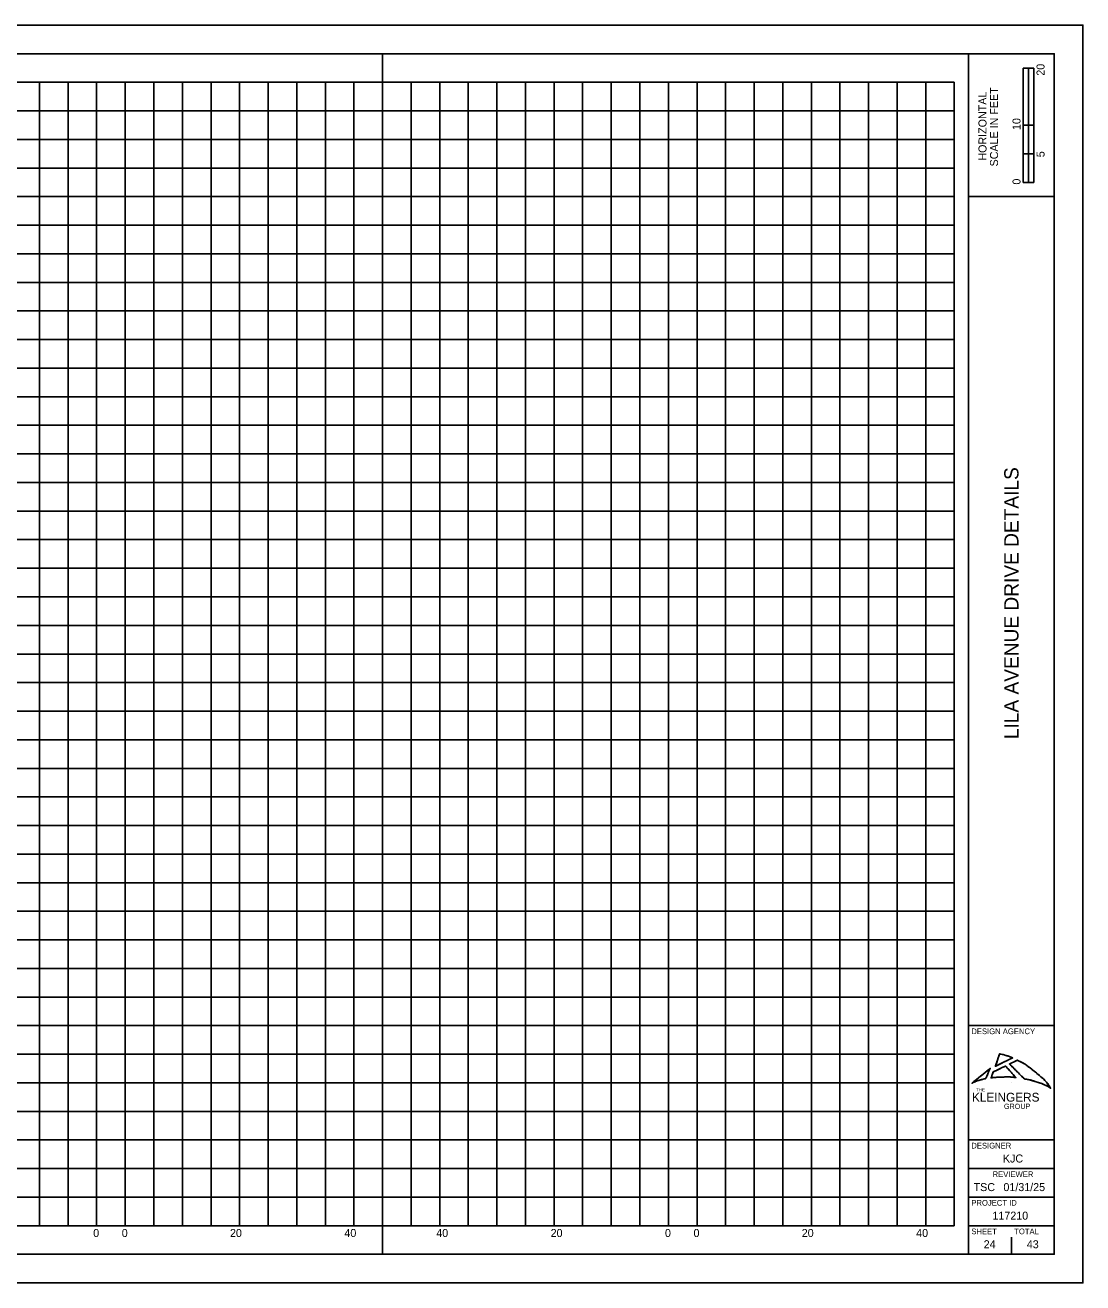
# Model space of a CAD drawing. Extents: x -2.9 to 34, y 0 to 23.9.
# Drawn here: x 15.5 to 34, y 0 to 22 of the extents above; entities that cross this region are included whole.
import ezdxf

# ---------------------------------------------------------------- set-up
doc = ezdxf.new("R2010")
doc.units = 0
for name, color, linetype in [('Default', 7, 'Continuous'), ('SH_Border', 7, 'Continuous'), ('SH_Cut_Line', 7, 'Continuous'), ('SH_Data', 7, 'Continuous'), ('SH_Major_Grid_Line', 7, 'Continuous')]:
    doc.layers.add(name, color=color, linetype=linetype)

msp = doc.modelspace()

# ---------------------------------------------------------------- linework, layer by layer
at = {"layer": 'Default'}
for points, degree in [([(32.542, 4.004), (32.542, 4.004), (32.47, 3.788), (32.47, 3.788)], 2), ([(32.772, 3.935), (32.772, 3.935), (32.722, 3.958), (32.655, 3.979), (32.588, 3.999), (32.542, 4.004), (32.542, 4.004), (32.542, 4.004), (32.47, 3.788), (32.47, 3.788), (32.47, 3.788), (32.772, 3.935), (32.772, 3.935)], 3), ([(32.772, 3.935), (32.772, 3.935), (32.722, 3.958), (32.655, 3.979)], 2), ([(32.379, 3.752), (32.379, 3.752), (32.061, 3.492), (32.061, 3.492)], 2), ([(32.379, 3.752), (32.379, 3.752), (32.061, 3.492), (32.061, 3.492), (32.061, 3.492), (32.133, 3.529), (32.21, 3.55), (32.28, 3.569), (32.303, 3.572), (32.303, 3.572), (32.303, 3.572), (32.379, 3.752), (32.379, 3.752)], 3), ([(32.303, 3.572), (32.303, 3.572), (32.379, 3.752), (32.379, 3.752)], 2), ([(32.648, 3.793), (32.648, 3.793), (32.83, 3.589), (32.83, 3.589), (32.83, 3.589), (32.734, 3.604), (32.602, 3.6), (32.455, 3.595), (32.396, 3.584), (32.396, 3.584), (32.396, 3.584), (32.434, 3.691), (32.434, 3.691), (32.434, 3.691), (32.648, 3.793), (32.648, 3.793)], 3), ([(32.434, 3.691), (32.434, 3.691), (32.648, 3.793), (32.648, 3.793)], 2), ([(32.47, 3.788), (32.47, 3.788), (32.772, 3.935), (32.772, 3.935)], 2), ([(32.648, 3.793), (32.648, 3.793), (32.83, 3.589), (32.83, 3.589)], 2), ([(33.2, 3.512), (33.079, 3.551), (32.978, 3.567), (32.978, 3.567), (32.978, 3.567), (32.717, 3.827), (32.717, 3.827), (32.717, 3.827), (32.855, 3.894), (32.855, 3.894), (32.855, 3.894), (32.985, 3.834), (33.142, 3.708), (33.348, 3.542), (33.438, 3.405), (33.438, 3.405), (33.438, 3.405), (33.351, 3.463), (33.2, 3.512)], 3), ([(32.717, 3.827), (32.717, 3.827), (32.855, 3.894), (32.855, 3.894)], 2), ([(32.978, 3.567), (32.978, 3.567), (32.717, 3.827), (32.717, 3.827)], 2), ([(32.855, 3.894), (32.855, 3.894), (32.985, 3.834), (33.142, 3.708)], 2), ([(32.061, 3.492), (32.061, 3.492), (32.133, 3.529), (32.21, 3.55)], 2), ([(32.21, 3.55), (32.28, 3.569), (32.303, 3.572), (32.303, 3.572)], 2), ([(32.396, 3.584), (32.396, 3.584), (32.434, 3.691), (32.434, 3.691)], 2), ([(32.602, 3.6), (32.455, 3.595), (32.396, 3.584), (32.396, 3.584)], 2), ([(32.83, 3.589), (32.83, 3.589), (32.734, 3.604), (32.602, 3.6)], 2), ([(33.2, 3.512), (33.079, 3.551), (32.978, 3.567), (32.978, 3.567)], 2), ([(33.142, 3.708), (33.348, 3.542), (33.438, 3.405), (33.438, 3.405)], 2), ([(33.438, 3.405), (33.438, 3.405), (33.351, 3.463), (33.2, 3.512)], 2)]:
    msp.add_open_spline(points, degree=degree, dxfattribs=at)
at = {"layer": 'SH_Border'}
for p, q in [((21.752, 0.5), (21.752, 21.5)), ((32, 0.5), (32, 21.5)), ((32, 19), (33.5, 19)), ((32, 4.5), (33.5, 4.5)), ((32, 2.5), (33.5, 2.5)), ((32, 2), (33.5, 2)), ((32, 1.5), (33.5, 1.5)), ((32, 1), (33.5, 1))]:
    msp.add_line(p, q, dxfattribs=at)
msp.add_lwpolyline([(1.5, 21.5), (33.5, 21.5), (33.5, 0.5), (1.5, 0.5)], close=True, dxfattribs=at)
at = {"layer": 'SH_Cut_Line'}
msp.add_lwpolyline([(0, 0), (34, 0), (34, 22), (0, 22)], close=True, dxfattribs=at)
at = {"layer": 'SH_Data'}
for p, q in [((32.957, 19.25), (32.957, 21.25)), ((33.144, 21.25), (32.957, 21.25)), ((32.957, 20.25), (32.957, 21.25)), ((32.957, 21.25), (33.05, 21.25)), ((33.05, 21.25), (33.051, 21.25)), ((33.051, 21.25), (33.051, 20.25)), ((33.144, 21.25), (33.144, 19.25)), ((33.051, 20.25), (32.957, 20.25)), ((33.143, 20.25), (33.05, 20.25)), ((33.05, 20.25), (33.05, 19.75)), ((33.143, 19.75), (33.143, 20.25)), ((33.05, 19.75), (32.957, 19.75)), ((32.957, 19.75), (32.957, 19.25)), ((33.05, 19.75), (33.143, 19.75)), ((33.05, 19.25), (33.05, 19.75)), ((33.144, 19.25), (32.957, 19.25)), ((32.957, 19.25), (33.05, 19.25)), ((32.75, 3.5), (32.75, 3.5)), ((32.375, 0.675), (32.375, 0.675)), ((32.75, 0.5), (32.75, 0.8))]:
    msp.add_line(p, q, dxfattribs=at)
at = {"layer": 'SH_Major_Grid_Line'}
for p, q in [((1.752, 21), (16.752, 21)), ((15.752, 11), (15.752, 21)), ((16.252, 11), (16.252, 21)), ((16.752, 11), (16.752, 21)), ((16.752, 11), (16.752, 21)), ((16.752, 21), (31.752, 21)), ((17.252, 11), (17.252, 21)), ((17.752, 11), (17.752, 21)), ((18.252, 11), (18.252, 21)), ((18.752, 11), (18.752, 21)), ((19.252, 11), (19.252, 21)), ((19.752, 11), (19.752, 21)), ((20.252, 11), (20.252, 21)), ((20.752, 11), (20.752, 21)), ((21.252, 11), (21.252, 21)), ((21.752, 11), (21.752, 21)), ((22.252, 11), (22.252, 21)), ((22.752, 11), (22.752, 21)), ((23.252, 11), (23.252, 21)), ((23.752, 11), (23.752, 21)), ((24.252, 11), (24.252, 21)), ((24.752, 11), (24.752, 21)), ((25.252, 11), (25.252, 21)), ((25.752, 11), (25.752, 21)), ((26.252, 11), (26.252, 21)), ((26.752, 11), (26.752, 21)), ((27.252, 11), (27.252, 21)), ((27.752, 11), (27.752, 21)), ((28.252, 11), (28.252, 21)), ((28.752, 11), (28.752, 21)), ((29.252, 11), (29.252, 21)), ((29.752, 11), (29.752, 21)), ((30.252, 11), (30.252, 21)), ((30.752, 11), (30.752, 21)), ((31.252, 11), (31.252, 21)), ((31.752, 11), (31.752, 21)), ((1.752, 20.5), (16.752, 20.5)), ((16.752, 20.5), (31.752, 20.5)), ((1.752, 20), (16.752, 20)), ((16.752, 20), (31.752, 20)), ((1.752, 19.5), (16.752, 19.5)), ((16.752, 19.5), (31.752, 19.5)), ((1.752, 19), (16.752, 19)), ((16.752, 19), (31.752, 19)), ((1.752, 18.5), (16.752, 18.5)), ((16.752, 18.5), (31.752, 18.5)), ((1.752, 18), (16.752, 18)), ((16.752, 18), (31.752, 18)), ((1.752, 17.5), (16.752, 17.5)), ((16.752, 17.5), (31.752, 17.5)), ((1.752, 17), (16.752, 17)), ((16.752, 17), (31.752, 17)), ((1.752, 16.5), (16.752, 16.5)), ((16.752, 16.5), (31.752, 16.5)), ((1.752, 16), (16.752, 16)), ((16.752, 16), (31.752, 16)), ((1.752, 15.5), (16.752, 15.5)), ((16.752, 15.5), (31.752, 15.5)), ((1.752, 15), (16.752, 15)), ((16.752, 15), (31.752, 15)), ((1.752, 14.5), (16.752, 14.5)), ((16.752, 14.5), (31.752, 14.5)), ((1.752, 14), (16.752, 14)), ((16.752, 14), (31.752, 14)), ((1.752, 13.5), (16.752, 13.5)), ((16.752, 13.5), (31.752, 13.5)), ((1.752, 13), (16.752, 13)), ((16.752, 13), (31.752, 13)), ((1.752, 12.5), (16.752, 12.5)), ((16.752, 12.5), (31.752, 12.5)), ((1.752, 12), (16.752, 12)), ((16.752, 12), (31.752, 12)), ((1.752, 11.5), (16.752, 11.5)), ((16.752, 11.5), (31.752, 11.5)), ((1.752, 11), (16.752, 11)), ((16.752, 11), (31.752, 11)), ((1.752, 11), (16.752, 11)), ((15.752, 1), (15.752, 11)), ((16.252, 1), (16.252, 11)), ((16.752, 11), (31.752, 11)), ((16.752, 1), (16.752, 11)), ((16.752, 1), (16.752, 11)), ((17.252, 1), (17.252, 11)), ((17.752, 1), (17.752, 11)), ((18.252, 1), (18.252, 11)), ((18.752, 1), (18.752, 11)), ((19.252, 1), (19.252, 11)), ((19.752, 1), (19.752, 11)), ((20.252, 1), (20.252, 11)), ((20.752, 1), (20.752, 11)), ((21.252, 1), (21.252, 11)), ((21.752, 1), (21.752, 11)), ((22.252, 1), (22.252, 11)), ((22.752, 1), (22.752, 11)), ((23.252, 1), (23.252, 11)), ((23.752, 1), (23.752, 11)), ((24.252, 1), (24.252, 11)), ((24.752, 1), (24.752, 11)), ((25.252, 1), (25.252, 11)), ((25.752, 1), (25.752, 11)), ((26.252, 1), (26.252, 11)), ((26.752, 1), (26.752, 11)), ((27.252, 1), (27.252, 11)), ((27.752, 1), (27.752, 11)), ((28.252, 1), (28.252, 11)), ((28.752, 1), (28.752, 11)), ((29.252, 1), (29.252, 11)), ((29.752, 1), (29.752, 11)), ((30.252, 1), (30.252, 11)), ((30.752, 1), (30.752, 11)), ((31.252, 1), (31.252, 11)), ((31.752, 1), (31.752, 11)), ((1.752, 10.5), (16.752, 10.5)), ((16.752, 10.5), (31.752, 10.5)), ((1.752, 10), (16.752, 10)), ((16.752, 10), (31.752, 10)), ((1.752, 9.5), (16.752, 9.5)), ((16.752, 9.5), (31.752, 9.5)), ((1.752, 9), (16.752, 9)), ((16.752, 9), (31.752, 9)), ((1.752, 8.5), (16.752, 8.5)), ((16.752, 8.5), (31.752, 8.5)), ((1.752, 8), (16.752, 8)), ((16.752, 8), (31.752, 8)), ((1.752, 7.5), (16.752, 7.5)), ((16.752, 7.5), (31.752, 7.5)), ((1.752, 7), (16.752, 7)), ((16.752, 7), (31.752, 7)), ((1.752, 6.5), (16.752, 6.5)), ((16.752, 6.5), (31.752, 6.5)), ((1.752, 6), (16.752, 6)), ((16.752, 6), (31.752, 6)), ((1.752, 5.5), (16.752, 5.5)), ((16.752, 5.5), (31.752, 5.5)), ((1.752, 5), (16.752, 5)), ((16.752, 5), (31.752, 5)), ((1.752, 4.5), (16.752, 4.5)), ((16.752, 4.5), (31.752, 4.5)), ((1.752, 4), (16.752, 4)), ((16.752, 4), (31.752, 4)), ((1.752, 3.5), (16.752, 3.5)), ((16.752, 3.5), (31.752, 3.5)), ((1.752, 3), (16.752, 3)), ((16.752, 3), (31.752, 3)), ((1.752, 2.5), (16.752, 2.5)), ((16.752, 2.5), (31.752, 2.5)), ((1.752, 2), (16.752, 2)), ((16.752, 2), (31.752, 2)), ((1.752, 1.5), (16.752, 1.5)), ((16.752, 1.5), (31.752, 1.5)), ((1.752, 1), (16.752, 1)), ((16.752, 1), (31.752, 1))]:
    msp.add_line(p, q, dxfattribs=at)

# ---------------------------------------------------------------- texts
at = {"layer": 'Default'}
for s, height, p in [('KLEINGERS', 0.1542, (32.061, 3.17)), ('THE', 0.0561, (32.135, 3.349)), ('GROUP', 0.0911, (32.62, 3.042))]:
    msp.add_text(s, height=height, dxfattribs=at).set_placement(p)
at = {"layer": 'SH_Border'}
for s, p in [('0', (16.692, 0.802)), ('0', (17.191, 0.802)), ('20', (19.084, 0.802)), ('40', (21.085, 0.802)), ('40', (22.692, 0.802)), ('20', (24.692, 0.802)), ('0', (26.692, 0.802)), ('0', (27.191, 0.802)), ('20', (29.084, 0.802)), ('40', (31.085, 0.802))]:
    msp.add_text(s, height=0.14, dxfattribs=at).set_placement(p)
at = {"layer": 'SH_Data'}
for s, height, p in [('20', 0.14, (33.33, 21.116)), ('SCALE IN FEET', 0.14, (32.517, 19.529)), ('HORIZONTAL', 0.14, (32.315, 19.63)), ('10', 0.14, (32.91, 20.166)), ('5', 0.14, (33.33, 19.69)), ('0', 0.14, (32.91, 19.211)), ('LILA AVENUE DRIVE DETAILS', 0.25, (32.875, 9.511))]:
    msp.add_text(s, height=height, rotation=90, dxfattribs=at).set_placement(p)
for s, height, p in [('DESIGN AGENCY', 0.1, (32.05, 4.35)), ('DESIGNER', 0.1, (32.05, 2.35)), ('KJC', 0.14, (32.602, 2.105)), ('REVIEWER', 0.1, (32.422, 1.85)), ('TSC', 0.14, (32.09, 1.605)), ('01/31/25', 0.14, (32.611, 1.605)), ('PROJECT ID', 0.1, (32.05, 1.35)), ('117210', 0.14, (32.419, 1.105)), ('SHEET', 0.1, (32.05, 0.85)), ('TOTAL', 0.1, (32.8, 0.85)), ('24', 0.14, (32.266, 0.605)), ('43', 0.14, (33.02, 0.605))]:
    msp.add_text(s, height=height, dxfattribs=at).set_placement(p)

doc.saveas('drawing.dxf')
